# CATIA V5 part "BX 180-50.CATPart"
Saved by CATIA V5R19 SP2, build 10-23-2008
Part number: BX 180-50
Bounding box of the stored display mesh (mm): x -24.865 to 24.865, y -24.997 to 24.997, z 0 to 220
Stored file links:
  C:\Users\Bora\Desktop\3D Katı model\BX serisi\BX 180\BX 180-50.CATPart
  C:\Program Files\Dassault Systemes\B19\intel_a\reffiles\standard\MetricThickPitch.txt
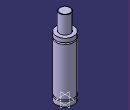
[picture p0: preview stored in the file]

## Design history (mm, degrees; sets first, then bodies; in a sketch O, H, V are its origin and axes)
Body1 (main body)
  Sketch1 on yz-plane, origin (0, 0, 0), H (0, 1, 0), V (0, 0, 1)
    point P2 (25, 12.5)
    line L1 (25, 12.5) -> (25, 0)
    point P3 (25, 16.5)
    point P4 (25, 153.5)
    line L2 (25, 153.5) -> (25, 16.5)
    point P6 (15, 219)
    arc A1 centre (14, 219) radius 1 from (15, 219) to (14, 220) ccw
    point P8 (15, 219)
    line L3 (15, 219) -> (15, 169)
    point P9 (25, 157.5)
    line L4 (25, 169) -> (25, 157.5)
    point P11 (25, 153.5)
    point P12 (25, 157.5)
    arc A2 centre (25, 155.5) radius 2 from (25, 157.5) to (25, 153.5) ccw
    point P13 (25, 12.5)
    point P14 (25, 16.5)
    arc A3 centre (25, 14.5) radius 2 from (25, 16.5) to (25, 12.5) ccw
    line L5 (14, 220) -> (0, 220)
    point P15 (0, 220)
    line L6 (15, 169) -> (25, 169)
    line L7 (25, 0) -> (0, 0)
    tangency: L5 A1
    coincidence: P15 V, P2 P13, P3 P14, P4 P11, P6 P8, P9 P12
    horizontal: L6 H, L7 H
  Shaft1: profile Sketch1, axis Sketch1.V, angle 360
  Sketch2 on face of Shaft1 from Sketch1.L7, origin (0, 0, 0), H (1, 0, 0), V (0, -1, 0)
    point P1 (12.5, 0)
    distance P1 V = 12.5
  Hole1: placed by Sketch2, at (12.5, 0, 0) direction (0, 0, 1), diameter 4.917, depth 6, threaded "M6", thread diameter 6, thread depth 6, pitch 1
  Sketch3 on face of Shaft1 from Sketch1.L7, origin (0, 0, 0), H (1, 0, 0), V (0, -1, 0)
    point P1 (-12.5, 0)
    distance P1 V = 12.5
  Hole2: placed by Sketch3, at (-12.5, 0, 0) direction (0, 0, 1), diameter 4.917, depth 6, threaded "M6", thread diameter 6, thread depth 6, pitch 1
